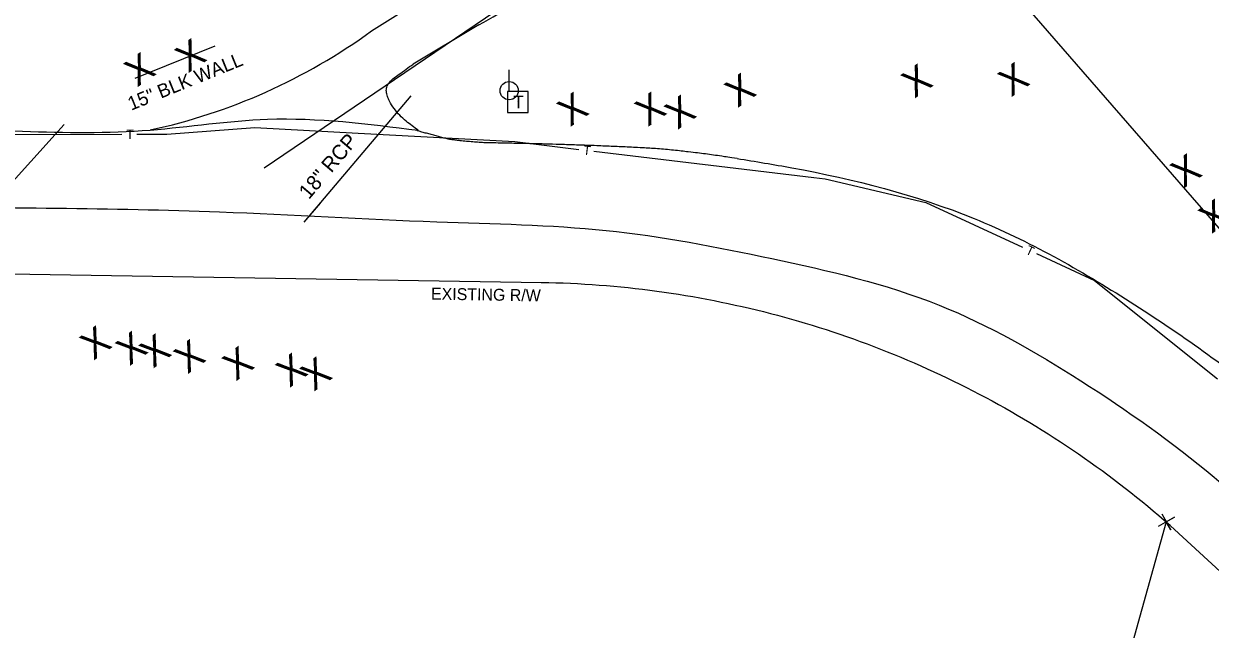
# Model space of a CAD drawing. Extents: x 1577032 to 1581865, y 611492 to 615011.
# Drawn here: x 1580555.6 to 1580874.3, y 613552.7 to 613715.4 of the extents above; entities that cross this region are included whole.
import ezdxf

# ---------------------------------------------------------------- set-up
doc = ezdxf.new("R2010")
doc.units = 0
for name, color, linetype in [('Exist Other Culture Area Outline', 7, 'Continuous'), ('Exist Other Culture Area Outline Text', 7, 'Continuous'), ('Exist Property Corner CELL', 7, 'Continuous'), ('Exist Property Line', 7, 'Continuous'), ('Exist Property Tie Line', 7, 'Continuous'), ('Exist Right of Way Line', 7, 'Continuous'), ('Exist Right of Way Line Text', 7, 'Continuous'), ('Exist Roads EOP', 7, 'Continuous'), ('Exist Roads Soil', 7, 'Continuous'), ('Exist Structure Minor Pipes RCP 18 Inch', 7, 'Continuous'), ('Exist Structure Minor Pipes RCP 18 Inch Text', 7, 'Continuous'), ('Exist Utilities Power Pole CELL', 7, 'Continuous'), ('Exist Utilities Telephone Pedestal CELL', 7, 'Continuous'), ('Exist Vegetation Tree CELL', 7, 'Continuous'), ('Old_Level_15', 7, 'Continuous')]:
    doc.layers.add(name, color=color, linetype=linetype)

msp = doc.modelspace()

# ---------------------------------------------------------------- linework, layer by layer
at = {"layer": 'Exist Other Culture Area Outline'}
msp.add_line((1580606.92, 613709.33), (1580585.44, 613700.61), dxfattribs=at)
at = {"layer": 'Exist Property Corner CELL'}
msp.add_line((1580862.44, 613581.59), (1580862.44, 613581.59), dxfattribs=at)
msp.add_lwpolyline([(1580861.21, 613583.77), (1580863.67, 613579.41), (1580862.44, 613581.59), (1580864.62, 613582.81), (1580860.26, 613580.36)], dxfattribs=at)
at = {"layer": 'Exist Property Line'}
msp.add_line((1580862.44, 613581.59), (1580402.42, 611938.06), dxfattribs=at)
at = {"layer": 'Exist Property Tie Line'}
for p, q in [((1580620.17, 613676.62), (1580772.66, 613780.09)), ((1580566.48, 613688.31), (1580530.61, 613648.57))]:
    msp.add_line(p, q, dxfattribs=at)
at = {"layer": 'Exist Right of Way Line'}
msp.add_line((1580772.66, 613780.09), (1580921.1, 613609.14), dxfattribs=at)
for points in [[(1580458.22, 613649.74), (1580694.67, 613645.91)], [(1580694.56, 613645.91), (1580696.62, 613645.87), (1580698.55, 613645.81), (1580700.5, 613645.75), (1580702.44, 613645.66), (1580704.38, 613645.57), (1580706.32, 613645.46), (1580708.26, 613645.33), (1580710.2, 613645.19), (1580712.14, 613645.04), (1580714.07, 613644.87), (1580716.01, 613644.69), (1580717.94, 613644.49), (1580719.87, 613644.28), (1580721.81, 613644.05), (1580723.73, 613643.81), (1580725.66, 613643.56), (1580727.59, 613643.29), (1580729.51, 613643.01), (1580731.43, 613642.71), (1580733.35, 613642.4), (1580735.27, 613642.07), (1580737.18, 613641.73), (1580739.09, 613641.38), (1580741, 613641.01), (1580742.91, 613640.63), (1580744.81, 613640.23), (1580746.71, 613639.82), (1580748.6, 613639.4), (1580750.5, 613638.96), (1580752.39, 613638.51), (1580754.27, 613638.04), (1580756.16, 613637.56), (1580758.04, 613637.06), (1580759.92, 613636.55), (1580761.79, 613636.03), (1580763.66, 613635.5), (1580765.52, 613634.95), (1580767.38, 613634.38), (1580769.24, 613633.8), (1580771.08, 613633.21), (1580772.93, 613632.61), (1580774.78, 613631.99), (1580776.62, 613631.36), (1580778.45, 613630.71), (1580780.28, 613630.05), (1580782.1, 613629.38), (1580783.92, 613628.69), (1580785.74, 613627.99), (1580787.53, 613627.28), (1580789.34, 613626.55), (1580791.14, 613625.8), (1580792.93, 613625.05), (1580794.72, 613624.29), (1580796.5, 613623.5), (1580798.27, 613622.71), (1580800.03, 613621.91), (1580801.8, 613621.08), (1580803.56, 613620.25), (1580805.3, 613619.41), (1580807.05, 613618.55), (1580808.79, 613617.67), (1580810.52, 613616.79), (1580812.24, 613615.89), (1580813.96, 613614.98), (1580815.67, 613614.06), (1580817.38, 613613.12), (1580819.07, 613612.18), (1580820.76, 613611.22), (1580822.45, 613610.24), (1580824.12, 613609.26), (1580825.79, 613608.26), (1580827.45, 613607.25), (1580829.1, 613606.22), (1580830.75, 613605.19), (1580832.38, 613604.14), (1580834.02, 613603.08), (1580835.63, 613602.01), (1580837.25, 613600.93), (1580838.86, 613599.83), (1580840.46, 613598.73), (1580842.04, 613597.61), (1580843.62, 613596.48), (1580845.2, 613595.34), (1580846.76, 613594.18), (1580848.31, 613593.02), (1580849.86, 613591.84), (1580851.4, 613590.65), (1580852.93, 613589.45), (1580854.45, 613588.24), (1580855.96, 613587.02), (1580857.46, 613585.78), (1580858.96, 613584.54), (1580860.44, 613583.28), (1580861.92, 613582.01), (1580863.46, 613580.66)], [(1580862.44, 613581.59), (1580885.91, 613560)]]:
    msp.add_lwpolyline(points, dxfattribs=at)
at = {"layer": 'Exist Roads EOP'}
for points in [[(1580513.43, 613688.06), (1580520.92, 613687.94), (1580589.58, 613686.82), (1580621.12, 613689.72), (1580661.54, 613686.76)], [(1580747.22, 613679.16), (1580761.93, 613676.67), (1580810.82, 613663.05), (1580852.74, 613640.68), (1580891.09, 613612.93), (1580922.25, 613584.25), (1580952.63, 613555.75)], [(1580403.71, 613668.15), (1580454.87, 613667.32), (1580520.57, 613666.25), (1580608.23, 613664.83), (1580666.57, 613662.17), (1580712.03, 613659.84), (1580756.49, 613652.31), (1580801.49, 613639.76), (1580839.51, 613619.48), (1580875.28, 613593.59), (1580905.28, 613565.99), (1580935.48, 613537.65)]]:
    msp.add_spline(points, degree=3, dxfattribs=at)
msp.add_open_spline([(1580747.22, 613679.16), (1580745.09, 613679.47), (1580742.95, 613679.78), (1580740.82, 613680.09), (1580738.68, 613680.4), (1580736.54, 613680.66), (1580734.4, 613680.91), (1580730.12, 613681.41), (1580725.83, 613681.82), (1580721.53, 613682.04), (1580719.35, 613682.16), (1580717.17, 613682.26), (1580714.99, 613682.36), (1580712.81, 613682.45), (1580710.63, 613682.55), (1580708.45, 613682.63), (1580704.09, 613682.79), (1580699.73, 613682.93), (1580695.37, 613683.05), (1580694.13, 613683.09), (1580692.9, 613683.12), (1580691.66, 613683.15), (1580690.42, 613683.17), (1580689.18, 613683.2), (1580687.94, 613683.22), (1580685.47, 613683.27), (1580682.99, 613683.33), (1580680.52, 613683.38), (1580679.66, 613683.4), (1580678.8, 613683.44), (1580677.94, 613683.49), (1580677.08, 613683.54), (1580676.22, 613683.61), (1580675.36, 613683.69), (1580674.5, 613683.77), (1580673.64, 613683.86), (1580672.78, 613683.96), (1580672.35, 613684.01), (1580671.93, 613684.06), (1580671.5, 613684.12), (1580671.07, 613684.17), (1580670.64, 613684.22), (1580670.21, 613684.29), (1580669.03, 613684.49), (1580667.88, 613684.83), (1580666.72, 613685.14), (1580665.41, 613685.48), (1580664.11, 613685.84), (1580662.8, 613686.2), (1580662.31, 613686.34), (1580661.83, 613686.5), (1580661.35, 613686.66), (1580661.28, 613686.68), (1580661.12, 613686.76), (1580661.54, 613686.76)], degree=3, dxfattribs=at)
at = {"layer": 'Exist Roads Soil'}
for p, q in [((1580649.02, 613713.42), (1580703.44, 613747.77)), ((1580677.87, 613715.03), (1580660.2, 613704.5))]:
    msp.add_line(p, q, dxfattribs=at)
msp.add_arc((1580556.27, 613840.99), 157.72, 282.1923, 306.0214, dxfattribs=at)
for points in [[(1580677.87, 613715.03), (1580718.61, 613739.05), (1580753.72, 613761.16), (1580787.54, 613781.82), (1580824.22, 613805.71), (1580849.76, 613822.58)], [(1580661.54, 613686.76), (1580658.34, 613689.19), (1580656.59, 613690.77), (1580655.07, 613692.58), (1580653.85, 613694.59), (1580653.31, 613695.86), (1580653.13, 613696.49), (1580653.01, 613697.13), (1580653.15, 613698.36), (1580653.42, 613698.97), (1580653.61, 613699.28), (1580653.83, 613699.58), (1580655.11, 613700.83), (1580656.46, 613701.79), (1580658.31, 613703.17), (1580660.2, 613704.5)]]:
    msp.add_spline(points, degree=3, dxfattribs=at)
at = {"layer": 'Exist Structure Minor Pipes RCP 18 Inch'}
for q in [(1580659.71, 613695.98), (1580635.29, 613667.19)]:
    msp.add_line((1580630.98, 613662.03), q, dxfattribs=at)
at = {"layer": 'Exist Utilities Power Pole CELL'}
for q in [(1580685.99, 613703.02), (1580685.99, 613697.4)]:
    msp.add_line((1580685.99, 613697.4), q, dxfattribs=at)
msp.add_circle((1580685.99, 613697.4), 2.45, dxfattribs=at)
at = {"layer": 'Exist Utilities Telephone Pedestal CELL'}
msp.add_line((1580688.25, 613694.36), (1580688.25, 613694.36), dxfattribs=at)
msp.add_lwpolyline([(1580685.52, 613691.53), (1580691.12, 613691.53), (1580691.12, 613697.13), (1580685.52, 613697.13), (1580685.52, 613691.53)], dxfattribs=at)
at = {"layer": 'Old_Level_15'}
for points in [[(1580522.49, 613685.63), (1580581.95, 613685.67)], [(1580586.05, 613685.67), (1580594.04, 613685.68), (1580617.67, 613687.48), (1580645.41, 613685.98)], [(1580645.41, 613685.98), (1580687.48, 613683.7), (1580704.69, 613681.63)], [(1580708.76, 613681.14), (1580767.8, 613674.05)], [(1580767.8, 613674.05), (1580770.83, 613673.68), (1580797.9, 613667.38), (1580823.86, 613655.34)], [(1580827.58, 613653.62), (1580843.19, 613646.38), (1580876.23, 613620.03)]]:
    msp.add_lwpolyline(points, dxfattribs=at)

# ---------------------------------------------------------------- texts
at = {"layer": 'Exist Other Culture Area Outline Text'}
msp.add_text('15" BLK WALL', height=3.6909, rotation=22.0977, dxfattribs=at).set_placement((1580584.48, 613691.98))
at = {"layer": 'Exist Right of Way Line Text'}
msp.add_text('EXISTING R/W', height=3.2, rotation=359.0711, dxfattribs=at).set_placement((1580664.98, 613641.28))
at = {"layer": 'Exist Structure Minor Pipes RCP 18 Inch Text'}
msp.add_text('18" RCP', height=4, rotation=49.7592, dxfattribs=at).set_placement((1580632.21, 613667.98))
at = {"layer": 'Exist Utilities Telephone Pedestal CELL'}
msp.add_text('T', height=3.42, dxfattribs=at).set_placement((1580687.11, 613692.65))
at = {"layer": 'Exist Vegetation Tree CELL'}
for rotation, p in [(34.1625, (1580599.71, 613701.98)), (34.1625, (1580586.07, 613698.24)), (34.1625, (1580794.75, 613695.17)), (34.1625, (1580820.73, 613695.54)), (34.1625, (1580747.3, 613692.7)), (34.1625, (1580702.34, 613687.58)), (34.1625, (1580723.19, 613687.6)), (34.1625, (1580731.18, 613686.82)), (34.1625, (1580867.01, 613671.03)), (34.1625, (1580874.57, 613658.88)), (35.6537, (1580574.34, 613624.83)), (35.6537, (1580583.99, 613623.35)), (35.6537, (1580590.32, 613622.68)), (35.6537, (1580599.56, 613621.16)), (35.6537, (1580612.59, 613619.29)), (35.6537, (1580626.96, 613617.49)), (35.6537, (1580633.52, 613616.5))]:
    msp.add_text('X', height=7.38, rotation=rotation, dxfattribs=at).set_placement(p)
at = {"layer": 'Old_Level_15'}
for rotation, p in [(0.0373, (1580583.18, 613684.44)), (353.1452, (1580705.76, 613680.26)), (335.1287, (1580824.46, 613653.71))]:
    msp.add_text('T', height=2.46, rotation=rotation, dxfattribs=at).set_placement(p)

doc.saveas('drawing.dxf')
